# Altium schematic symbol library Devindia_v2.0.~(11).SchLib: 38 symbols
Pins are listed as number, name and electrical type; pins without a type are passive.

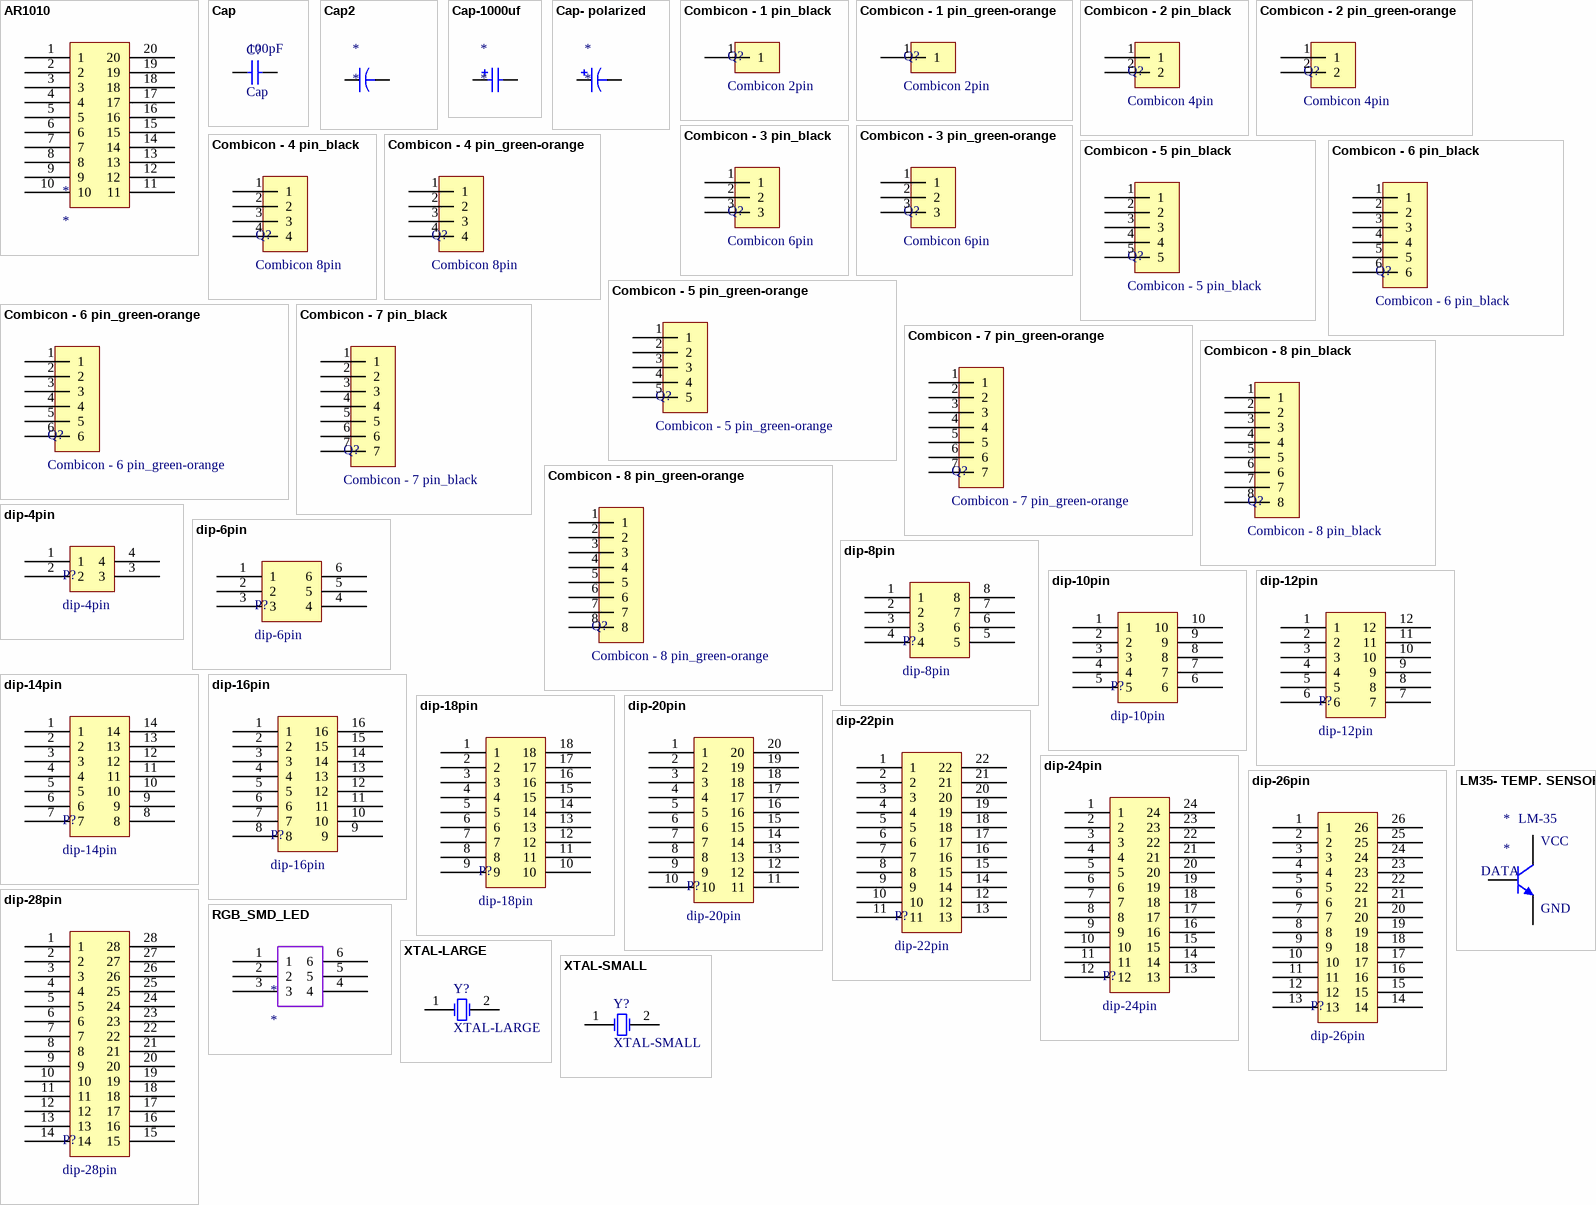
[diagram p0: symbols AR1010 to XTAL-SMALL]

## AR1010
designator *
footprint AR1010
pins: 1, 2, 3, 4, 5, 6, 7, 8, 9, 10, 11, 12, 13, 14, 15, 16, 17, 18, 19, 20

## Cap
designator C?  value 100pF
Capacitor
footprint Cap
footprint CAPR2.54-5.1x3.2 (Capacitor, Ceramic, Thru-Hole, Dipped Radial; Body 5.1 x 3.2 mm (WxT) Pin Spacing 2.54 mm (typ))
footprint CAPR5.08-7.8x3.2 (Capacitor, Ceramic, Thru-Hole, Dipped Radial; Body 7.8 x 3.2 mm (WxT) Pin Spacing 5.08 mm (typ))
simulation model CAP (Capacitor)
signal-integrity model Cap
pins: 1, 2

## Cap2
designator *
pins: 1, 2

## Cap-1000uf
designator *
pins: 1, 2

## Cap- polarized
designator *
pins: 1, 2

## Combicon - 1 pin_black
designator Q?, comment Combicon 2pin
footprint Combicon - 2 pin
pins: 1

## Combicon - 1 pin_green-orange
designator Q?, comment Combicon 2pin
footprint Combicon - 2 pin
pins: 1

## Combicon - 2 pin_black
designator Q?, comment Combicon 4pin
footprint Combicon - 4pin
pins: 1, 2

## Combicon - 2 pin_green-orange
designator Q?, comment Combicon 4pin
footprint Combicon - 4pin
pins: 1, 2

## Combicon - 3 pin_black
designator Q?, comment Combicon 6pin
footprint Combicon - 6pin
pins: 1, 2, 3

## Combicon - 3 pin_green-orange
designator Q?, comment Combicon 6pin
footprint Combicon - 6pin
pins: 1, 2, 3

## Combicon - 4 pin_black
designator Q?, comment Combicon 8pin
footprint Combicon - 8pin
pins: 1, 2, 3, 4

## Combicon - 4 pin_green-orange
designator Q?, comment Combicon 8pin
footprint Combicon - 8pin
pins: 1, 2, 3, 4

## Combicon - 5 pin_black
designator Q?
footprint Combicon - 10 pin
pins: 1, 2, 3, 4, 5

## Combicon - 5 pin_green-orange
designator Q?
footprint Combicon - 10 pin
pins: 1, 2, 3, 4, 5

## Combicon - 6 pin_black
designator Q?
footprint Combicon - 12pin
pins: 1, 2, 3, 4, 5, 6

## Combicon - 6 pin_green-orange
designator Q?
footprint Combicon - 12pin
pins: 1, 2, 3, 4, 5, 6

## Combicon - 7 pin_black
designator Q?
footprint Combicon - 14pin
pins: 1, 2, 3, 4, 5, 6, 7

## Combicon - 7 pin_green-orange
designator Q?
footprint Combicon - 14pin
pins: 1, 2, 3, 4, 5, 6, 7

## Combicon - 8 pin_black
designator Q?
footprint Combicon - 16pin
pins: 1, 2, 3, 4, 5, 6, 7, 8

## Combicon - 8 pin_green-orange
designator Q?
footprint Combicon - 16pin
pins: 1, 2, 3, 4, 5, 6, 7, 8

## dip-4pin
designator P?
footprint dip-4pin
pins: 1, 2, 3, 4

## dip-6pin
designator P?
footprint dip-6pin
pins: 1, 2, 3, 4, 5, 6

## dip-8pin
designator P?
footprint dip-8pin
pins: 1, 2, 3, 4, 5, 6, 7, 8

## dip-10pin
designator P?
footprint dip-10pin
pins: 1, 2, 3, 4, 5, 6, 7, 8, 9, 10

## dip-12pin
designator P?
footprint dip-12pin
pins: 1, 2, 3, 4, 5, 6, 7, 8, 9, 10, 11, 12

## dip-14pin
designator P?
footprint dip-14pin
pins: 1, 2, 3, 4, 5, 6, 7, 8, 9, 10, 11, 12, 13, 14

## dip-16pin
designator P?
footprint dip-16pin
pins: 1, 2, 3, 4, 5, 6, 7, 8, 9, 10, 11, 12, 13, 14, 15, 16

## dip-18pin
designator P?
footprint dip-18pin
pins: 1, 2, 3, 4, 5, 6, 7, 8, 9, 10, 11, 12, 13, 14, 15, 16, 17, 18

## dip-20pin
designator P?
footprint dip-20pin
pins: 1, 2, 3, 4, 5, 6, 7, 8, 9, 10, 11, 12, 13, 14, 15, 16, 17, 18, 19, 20

## dip-22pin
designator P?
footprint dip-22pin
pins: 1, 2, 3, 4, 5, 6, 7, 8, 9, 10, 11, 12, 13, 14, 15, 16, 17, 18, 19, 20, 21, 22

## dip-24pin
designator P?
footprint dip-24pin
pins: 1, 2, 3, 4, 5, 6, 7, 8, 9, 10, 11, 12, 13, 14, 15, 16, 17, 18, 19, 20, 21, 22, 23, 24

## dip-26pin
designator P?
footprint dip-26pin
pins: 1, 2, 3, 4, 5, 6, 7, 8, 9, 10, 11, 12, 13, 14, 15, 16, 17, 18, 19, 20, 21, 22, 23, 24, 25, 26

## dip-28pin
designator P?
footprint dip-28pin
pins: 1, 2, 3, 4, 5, 6, 7, 8, 9, 10, 11, 12, 13, 14, 15, 16, 17, 18, 19, 20, 21, 22, 23, 24, 25, 26, 27, 28

## LM35- TEMP. SENSOR
designator *
pins: 1 E, 2 B, 3 C

## RGB_SMD_LED
designator *
footprint RGB_SMD_LED
pins: 1, 2, 3, 4, 5, 6

## XTAL-LARGE
designator Y?
Crystal Oscillator
footprint CRYSTAL3
simulation model XTAL (Spice Subcircuit)
pins: 1 OSC1, 2 OSC2

## XTAL-SMALL
designator Y?
Crystal Oscillator
footprint CRYSTAL1
simulation model XTAL (Spice Subcircuit)
pins: 1 OSC1, 2 OSC2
